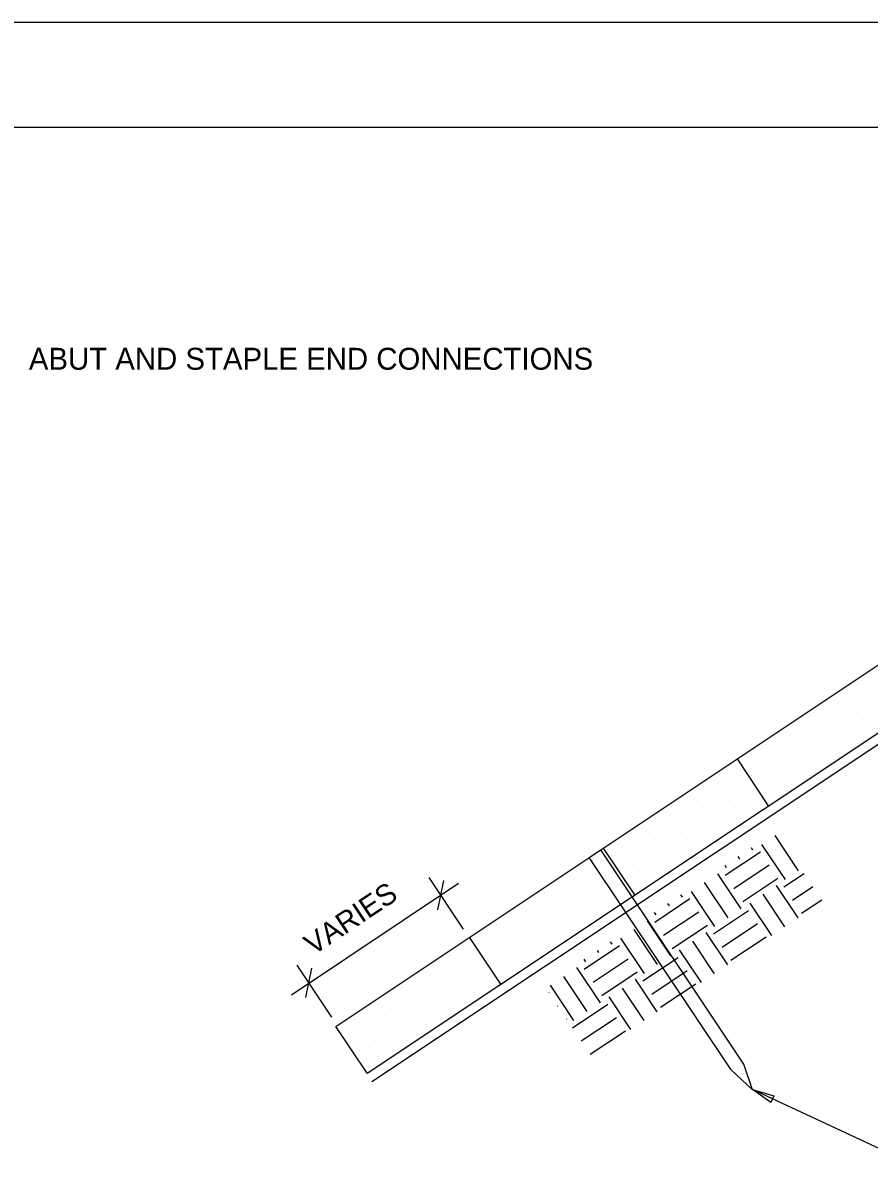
# Model space of a CAD drawing. Extents: x 638850 to 644908, y 297188 to 298900.
# Drawn here: x 641612.1 to 641721.5, y 297724.8 to 297871.3 of the extents above; entities that cross this region are included whole.
import ezdxf

# ---------------------------------------------------------------- set-up
doc = ezdxf.new("R2010")
doc.units = 0
for name, color, linetype in [('1', 7, 'Continuous'), ('11', 7, 'Continuous'), ('12', 7, 'Continuous'), ('3', 7, 'Continuous'), ('4', 7, 'Continuous'), ('5', 7, 'Continuous'), ('6', 7, 'Continuous'), ('7', 7, 'Continuous')]:
    doc.layers.add(name, color=color, linetype=linetype)

msp = doc.modelspace()

# ---------------------------------------------------------------- linework, layer by layer
at = {"layer": '1'}
for p, q in [((642242.46, 297871.34), (641270.46, 297871.34)), ((641310.96, 297857.84), (642228.96, 297857.84))]:
    msp.add_line(p, q, dxfattribs=at)
at = {"layer": '11'}
for p, q in [((641718.5, 297784.91), (641718.5, 297784.91)), ((641719.87, 297784.91), (641719.87, 297784.91)), ((641720.55, 297786.28), (641720.55, 297786.28)), ((641721.24, 297784.91), (641721.24, 297784.91)), ((641716.45, 297783.54), (641716.45, 297783.54)), ((641717.82, 297783.54), (641717.82, 297783.54)), ((641719.19, 297783.54), (641719.19, 297783.54)), ((641720.55, 297783.54), (641720.55, 297783.54)), ((641714.4, 297782.17), (641714.4, 297782.17)), ((641715.77, 297782.17), (641715.77, 297782.17)), ((641717.13, 297782.17), (641717.13, 297782.17)), ((641718.5, 297782.17), (641718.5, 297782.17)), ((641719.87, 297782.17), (641719.87, 297782.17)), ((641721.24, 297782.17), (641721.24, 297782.17)), ((641712.35, 297780.81), (641712.35, 297780.81)), ((641713.72, 297780.81), (641713.72, 297780.81)), ((641715.08, 297780.81), (641715.08, 297780.81)), ((641716.45, 297780.81), (641716.45, 297780.81)), ((641717.82, 297780.81), (641717.82, 297780.81)), ((641719.19, 297780.81), (641719.19, 297780.81)), ((641720.55, 297780.81), (641720.55, 297780.81)), ((641710.3, 297779.44), (641710.3, 297779.44)), ((641711.67, 297779.44), (641711.67, 297779.44)), ((641713.04, 297779.44), (641713.04, 297779.44)), ((641714.4, 297779.44), (641714.4, 297779.44)), ((641715.77, 297779.44), (641715.77, 297779.44)), ((641717.13, 297779.44), (641717.13, 297779.44)), ((641718.5, 297779.44), (641718.5, 297779.44)), ((641719.87, 297779.44), (641719.87, 297779.44)), ((641721.24, 297779.44), (641721.24, 297779.44)), ((641708.25, 297778.07), (641708.25, 297778.07)), ((641709.62, 297778.07), (641709.62, 297778.07)), ((641710.98, 297778.07), (641710.98, 297778.07)), ((641712.35, 297778.07), (641712.35, 297778.07)), ((641713.72, 297778.07), (641713.72, 297778.07)), ((641715.08, 297778.07), (641715.08, 297778.07)), ((641716.45, 297778.07), (641716.45, 297778.07)), ((641717.82, 297778.07), (641717.82, 297778.07)), ((641719.19, 297778.07), (641719.19, 297778.07)), ((641706.2, 297776.71), (641706.2, 297776.71)), ((641707.57, 297776.71), (641707.57, 297776.71)), ((641708.93, 297776.71), (641708.93, 297776.71)), ((641710.3, 297776.71), (641710.3, 297776.71)), ((641711.67, 297776.71), (641711.67, 297776.71)), ((641713.04, 297776.71), (641713.04, 297776.71)), ((641714.4, 297776.71), (641714.4, 297776.71)), ((641715.77, 297776.71), (641715.77, 297776.71)), ((641717.13, 297776.71), (641717.13, 297776.71)), ((641704.15, 297775.34), (641704.15, 297775.34)), ((641705.52, 297775.34), (641705.52, 297775.34)), ((641706.88, 297775.34), (641706.88, 297775.34)), ((641708.25, 297775.34), (641708.25, 297775.34)), ((641709.62, 297775.34), (641709.62, 297775.34)), ((641710.98, 297775.34), (641710.98, 297775.34)), ((641712.35, 297775.34), (641712.35, 297775.34)), ((641713.72, 297775.34), (641713.72, 297775.34)), ((641715.08, 297775.34), (641715.08, 297775.34)), ((641702.1, 297773.97), (641702.1, 297773.97)), ((641703.47, 297773.97), (641703.47, 297773.97)), ((641704.83, 297773.97), (641704.83, 297773.97)), ((641706.2, 297773.97), (641706.2, 297773.97)), ((641707.57, 297773.97), (641707.57, 297773.97)), ((641708.93, 297773.97), (641708.93, 297773.97)), ((641710.3, 297773.97), (641710.3, 297773.97)), ((641711.67, 297773.97), (641711.67, 297773.97)), ((641713.04, 297773.97), (641713.04, 297773.97)), ((641700.05, 297772.61), (641700.05, 297772.61)), ((641701.42, 297772.61), (641701.42, 297772.61)), ((641702.78, 297772.61), (641702.78, 297772.61)), ((641704.15, 297772.61), (641704.15, 297772.61)), ((641705.52, 297772.61), (641705.52, 297772.61)), ((641706.88, 297772.61), (641706.88, 297772.61)), ((641708.25, 297772.61), (641708.25, 297772.61)), ((641709.62, 297772.61), (641709.62, 297772.61)), ((641710.98, 297772.61), (641710.98, 297772.61)), ((641698, 297771.24), (641698, 297771.24)), ((641699.37, 297771.24), (641699.37, 297771.24)), ((641700.73, 297771.24), (641700.73, 297771.24)), ((641702.1, 297771.24), (641702.1, 297771.24)), ((641703.47, 297771.24), (641703.47, 297771.24)), ((641704.83, 297771.24), (641704.83, 297771.24)), ((641706.2, 297771.24), (641706.2, 297771.24)), ((641707.57, 297771.24), (641707.57, 297771.24)), ((641708.93, 297771.24), (641708.93, 297771.24)), ((641695.95, 297769.87), (641695.95, 297769.87)), ((641697.32, 297769.87), (641697.32, 297769.87)), ((641698.68, 297769.87), (641698.68, 297769.87)), ((641700.05, 297769.87), (641700.05, 297769.87)), ((641701.42, 297769.87), (641701.42, 297769.87)), ((641702.78, 297769.87), (641702.78, 297769.87)), ((641704.15, 297769.87), (641704.15, 297769.87)), ((641705.52, 297769.87), (641705.52, 297769.87)), ((641706.88, 297769.87), (641706.88, 297769.87)), ((641693.9, 297768.51), (641693.9, 297768.51)), ((641695.26, 297768.51), (641695.26, 297768.51)), ((641696.63, 297768.51), (641696.63, 297768.51)), ((641698, 297768.51), (641698, 297768.51)), ((641699.37, 297768.51), (641699.37, 297768.51)), ((641700.73, 297768.51), (641700.73, 297768.51)), ((641702.1, 297768.51), (641702.1, 297768.51)), ((641703.47, 297768.51), (641703.47, 297768.51)), ((641704.83, 297768.51), (641704.83, 297768.51)), ((641691.85, 297767.14), (641691.85, 297767.14)), ((641693.21, 297767.14), (641693.21, 297767.14)), ((641694.58, 297767.14), (641694.58, 297767.14)), ((641695.95, 297767.14), (641695.95, 297767.14)), ((641697.32, 297767.14), (641697.32, 297767.14)), ((641698.68, 297767.14), (641698.68, 297767.14)), ((641700.05, 297767.14), (641700.05, 297767.14)), ((641701.42, 297767.14), (641701.42, 297767.14)), ((641702.78, 297767.14), (641702.78, 297767.14)), ((641687.75, 297764.41), (641687.75, 297764.41)), ((641689.11, 297764.41), (641689.11, 297764.41)), ((641689.8, 297765.77), (641689.8, 297765.77)), ((641690.48, 297764.41), (641690.48, 297764.41)), ((641691.17, 297765.77), (641691.17, 297765.77)), ((641691.85, 297764.41), (641691.85, 297764.41)), ((641692.53, 297765.77), (641692.53, 297765.77)), ((641693.21, 297764.41), (641693.21, 297764.41)), ((641693.9, 297765.77), (641693.9, 297765.77)), ((641694.58, 297764.41), (641694.58, 297764.41)), ((641695.26, 297765.77), (641695.26, 297765.77)), ((641695.95, 297764.41), (641695.95, 297764.41)), ((641696.63, 297765.77), (641696.63, 297765.77)), ((641697.32, 297764.41), (641697.32, 297764.41)), ((641698, 297765.77), (641698, 297765.77)), ((641698.68, 297764.41), (641698.68, 297764.41)), ((641699.37, 297765.77), (641699.37, 297765.77)), ((641700.73, 297765.77), (641700.73, 297765.77)), ((641685.7, 297763.04), (641685.7, 297763.04)), ((641687.06, 297763.04), (641687.06, 297763.04)), ((641688.43, 297763.04), (641688.43, 297763.04)), ((641689.8, 297763.04), (641689.8, 297763.04)), ((641691.17, 297763.04), (641691.17, 297763.04)), ((641692.53, 297763.04), (641692.53, 297763.04)), ((641693.9, 297763.04), (641693.9, 297763.04)), ((641695.26, 297763.04), (641695.26, 297763.04)), ((641696.63, 297763.04), (641696.63, 297763.04)), ((641683.65, 297761.67), (641683.65, 297761.67)), ((641685.01, 297761.67), (641685.01, 297761.67)), ((641686.38, 297761.67), (641686.38, 297761.67)), ((641687.75, 297761.67), (641687.75, 297761.67)), ((641689.11, 297761.67), (641689.11, 297761.67)), ((641690.48, 297761.67), (641690.48, 297761.67)), ((641691.85, 297761.67), (641691.85, 297761.67)), ((641693.21, 297761.67), (641693.21, 297761.67)), ((641694.58, 297761.67), (641694.58, 297761.67)), ((641681.6, 297760.3), (641681.6, 297760.3)), ((641682.96, 297760.3), (641682.96, 297760.3)), ((641684.33, 297760.3), (641684.33, 297760.3)), ((641685.7, 297760.3), (641685.7, 297760.3)), ((641687.06, 297760.3), (641687.06, 297760.3)), ((641688.43, 297760.3), (641688.43, 297760.3)), ((641689.8, 297760.3), (641689.8, 297760.3)), ((641691.17, 297760.3), (641691.17, 297760.3)), ((641692.53, 297760.3), (641692.53, 297760.3)), ((641679.55, 297758.94), (641679.55, 297758.94)), ((641680.91, 297758.94), (641680.91, 297758.94)), ((641682.28, 297758.94), (641682.28, 297758.94)), ((641683.65, 297758.94), (641683.65, 297758.94)), ((641685.01, 297758.94), (641685.01, 297758.94)), ((641686.38, 297758.94), (641686.38, 297758.94)), ((641687.75, 297758.94), (641687.75, 297758.94)), ((641689.11, 297758.94), (641689.11, 297758.94)), ((641690.48, 297758.94), (641690.48, 297758.94)), ((641677.5, 297757.57), (641677.5, 297757.57)), ((641678.86, 297757.57), (641678.86, 297757.57)), ((641680.23, 297757.57), (641680.23, 297757.57)), ((641681.6, 297757.57), (641681.6, 297757.57)), ((641682.96, 297757.57), (641682.96, 297757.57)), ((641684.33, 297757.57), (641684.33, 297757.57)), ((641685.7, 297757.57), (641685.7, 297757.57)), ((641687.06, 297757.57), (641687.06, 297757.57)), ((641688.43, 297757.57), (641688.43, 297757.57)), ((641675.45, 297756.2), (641675.45, 297756.2)), ((641676.81, 297756.2), (641676.81, 297756.2)), ((641678.18, 297756.2), (641678.18, 297756.2)), ((641679.55, 297756.2), (641679.55, 297756.2)), ((641680.91, 297756.2), (641680.91, 297756.2)), ((641682.28, 297756.2), (641682.28, 297756.2)), ((641683.65, 297756.2), (641683.65, 297756.2)), ((641685.01, 297756.2), (641685.01, 297756.2)), ((641686.38, 297756.2), (641686.38, 297756.2)), ((641673.39, 297754.84), (641673.39, 297754.84)), ((641674.76, 297754.84), (641674.76, 297754.84)), ((641676.13, 297754.84), (641676.13, 297754.84)), ((641677.5, 297754.84), (641677.5, 297754.84)), ((641678.86, 297754.84), (641678.86, 297754.84)), ((641680.23, 297754.84), (641680.23, 297754.84)), ((641681.6, 297754.84), (641681.6, 297754.84)), ((641682.96, 297754.84), (641682.96, 297754.84)), ((641684.33, 297754.84), (641684.33, 297754.84)), ((641671.34, 297753.47), (641671.34, 297753.47)), ((641672.71, 297753.47), (641672.71, 297753.47)), ((641674.08, 297753.47), (641674.08, 297753.47)), ((641675.45, 297753.47), (641675.45, 297753.47)), ((641676.81, 297753.47), (641676.81, 297753.47)), ((641678.18, 297753.47), (641678.18, 297753.47)), ((641679.55, 297753.47), (641679.55, 297753.47)), ((641680.91, 297753.47), (641680.91, 297753.47)), ((641682.28, 297753.47), (641682.28, 297753.47)), ((641669.3, 297752.1), (641669.3, 297752.1)), ((641670.66, 297752.1), (641670.66, 297752.1)), ((641672.03, 297752.1), (641672.03, 297752.1)), ((641673.39, 297752.1), (641673.39, 297752.1)), ((641674.76, 297752.1), (641674.76, 297752.1)), ((641676.13, 297752.1), (641676.13, 297752.1)), ((641677.5, 297752.1), (641677.5, 297752.1)), ((641678.86, 297752.1), (641678.86, 297752.1)), ((641680.23, 297752.1), (641680.23, 297752.1)), ((641667.24, 297750.74), (641667.24, 297750.74)), ((641668.61, 297750.74), (641668.61, 297750.74)), ((641669.98, 297750.74), (641669.98, 297750.74)), ((641671.34, 297750.74), (641671.34, 297750.74)), ((641672.71, 297750.74), (641672.71, 297750.74)), ((641674.08, 297750.74), (641674.08, 297750.74)), ((641675.45, 297750.74), (641675.45, 297750.74)), ((641676.81, 297750.74), (641676.81, 297750.74)), ((641678.18, 297750.74), (641678.18, 297750.74)), ((641665.19, 297749.37), (641665.19, 297749.37)), ((641666.56, 297749.37), (641666.56, 297749.37)), ((641667.93, 297749.37), (641667.93, 297749.37)), ((641669.3, 297749.37), (641669.3, 297749.37)), ((641670.66, 297749.37), (641670.66, 297749.37)), ((641672.03, 297749.37), (641672.03, 297749.37)), ((641673.39, 297749.37), (641673.39, 297749.37)), ((641674.76, 297749.37), (641674.76, 297749.37)), ((641676.13, 297749.37), (641676.13, 297749.37)), ((641663.14, 297748), (641663.14, 297748)), ((641664.51, 297748), (641664.51, 297748)), ((641665.88, 297748), (641665.88, 297748)), ((641667.24, 297748), (641667.24, 297748)), ((641668.61, 297748), (641668.61, 297748)), ((641669.98, 297748), (641669.98, 297748)), ((641671.34, 297748), (641671.34, 297748)), ((641672.71, 297748), (641672.71, 297748)), ((641674.08, 297748), (641674.08, 297748)), ((641661.09, 297746.64), (641661.09, 297746.64)), ((641662.46, 297746.64), (641662.46, 297746.64)), ((641663.83, 297746.64), (641663.83, 297746.64)), ((641665.19, 297746.64), (641665.19, 297746.64)), ((641666.56, 297746.64), (641666.56, 297746.64)), ((641667.93, 297746.64), (641667.93, 297746.64)), ((641669.3, 297746.64), (641669.3, 297746.64)), ((641670.66, 297746.64), (641670.66, 297746.64)), ((641672.03, 297746.64), (641672.03, 297746.64)), ((641656.99, 297743.9), (641656.99, 297743.9)), ((641658.36, 297743.9), (641658.36, 297743.9)), ((641659.04, 297745.27), (641659.04, 297745.27)), ((641659.73, 297743.9), (641659.73, 297743.9)), ((641660.41, 297745.27), (641660.41, 297745.27)), ((641661.09, 297743.9), (641661.09, 297743.9)), ((641661.78, 297745.27), (641661.78, 297745.27)), ((641662.46, 297743.9), (641662.46, 297743.9)), ((641663.14, 297745.27), (641663.14, 297745.27)), ((641663.83, 297743.9), (641663.83, 297743.9)), ((641664.51, 297745.27), (641664.51, 297745.27)), ((641665.19, 297743.9), (641665.19, 297743.9)), ((641665.88, 297745.27), (641665.88, 297745.27)), ((641666.56, 297743.9), (641666.56, 297743.9)), ((641667.24, 297745.27), (641667.24, 297745.27)), ((641667.93, 297743.9), (641667.93, 297743.9)), ((641668.61, 297745.27), (641668.61, 297745.27)), ((641669.98, 297745.27), (641669.98, 297745.27)), ((641654.94, 297742.54), (641654.94, 297742.54)), ((641656.31, 297742.54), (641656.31, 297742.54)), ((641657.68, 297742.54), (641657.68, 297742.54)), ((641659.04, 297742.54), (641659.04, 297742.54)), ((641660.41, 297742.54), (641660.41, 297742.54)), ((641661.78, 297742.54), (641661.78, 297742.54)), ((641663.14, 297742.54), (641663.14, 297742.54)), ((641664.51, 297742.54), (641664.51, 297742.54)), ((641665.88, 297742.54), (641665.88, 297742.54)), ((641652.89, 297741.17), (641652.89, 297741.17)), ((641654.26, 297741.17), (641654.26, 297741.17)), ((641655.63, 297741.17), (641655.63, 297741.17)), ((641656.99, 297741.17), (641656.99, 297741.17)), ((641658.36, 297741.17), (641658.36, 297741.17)), ((641659.73, 297741.17), (641659.73, 297741.17)), ((641661.09, 297741.17), (641661.09, 297741.17)), ((641662.46, 297741.17), (641662.46, 297741.17)), ((641663.83, 297741.17), (641663.83, 297741.17)), ((641654.94, 297739.8), (641654.94, 297739.8)), ((641656.31, 297739.8), (641656.31, 297739.8)), ((641657.68, 297739.8), (641657.68, 297739.8)), ((641659.04, 297739.8), (641659.04, 297739.8)), ((641660.41, 297739.8), (641660.41, 297739.8)), ((641661.78, 297739.8), (641661.78, 297739.8)), ((641655.63, 297738.43), (641655.63, 297738.43)), ((641656.99, 297738.43), (641656.99, 297738.43)), ((641658.36, 297738.43), (641658.36, 297738.43)), ((641659.73, 297738.43), (641659.73, 297738.43)), ((641656.31, 297737.07), (641656.31, 297737.07)), ((641657.68, 297737.07), (641657.68, 297737.07))]:
    msp.add_line(p, q, dxfattribs=at)
at = {"layer": '12'}
for p, q in [((641712.33, 297761.72), (641709.3, 297766.27)), ((641706.45, 297764.37), (641706.25, 297764.69)), ((641710.63, 297760.58), (641707.59, 297765.13)), ((641702.85, 297761.15), (641707.4, 297764.18)), ((641704.75, 297763.24), (641704.54, 297763.55)), ((641703.04, 297762.1), (641702.84, 297762.41)), ((641703.99, 297759.44), (641708.54, 297762.48)), ((641703.24, 297755.65), (641700.2, 297760.2)), ((641704.94, 297756.79), (641701.91, 297761.34)), ((641705.13, 297757.74), (641709.68, 297760.77)), ((641710.44, 297759.64), (641713.06, 297761.38)), ((641697.36, 297758.31), (641697.15, 297758.62)), ((641701.53, 297754.52), (641698.49, 297759.06)), ((641710.58, 297754.49), (641707.78, 297758.69)), ((641712.29, 297755.62), (641709.49, 297759.82)), ((641711.57, 297757.93), (641714.19, 297759.68)), ((641693.76, 297755.08), (641698.31, 297758.12)), ((641695.65, 297757.17), (641695.44, 297757.48)), ((641708.88, 297753.35), (641706.08, 297757.55)), ((641712.71, 297756.22), (641715.33, 297757.97)), ((641693.95, 297756.03), (641693.74, 297756.34)), ((641694.89, 297753.38), (641699.44, 297756.41)), ((641701.34, 297753.57), (641705.89, 297756.6)), ((641694.14, 297749.59), (641691.1, 297754.14)), ((641695.84, 297750.72), (641692.81, 297755.27)), ((641696.03, 297751.67), (641700.58, 297754.7)), ((641702.48, 297751.86), (641707.03, 297754.89)), ((641692.43, 297748.45), (641689.4, 297753)), ((641701.49, 297748.42), (641698.69, 297752.62)), ((641703.19, 297749.56), (641700.39, 297753.76)), ((641703.61, 297750.15), (641708.16, 297753.19)), ((641684.66, 297749.02), (641689.21, 297752.05)), ((641686.56, 297751.1), (641686.35, 297751.41)), ((641688.26, 297752.24), (641688.05, 297752.55)), ((641699.78, 297747.28), (641696.98, 297751.48)), ((641684.85, 297749.96), (641684.64, 297750.28)), ((641685.8, 297747.31), (641690.35, 297750.34)), ((641692.24, 297747.5), (641696.79, 297750.53)), ((641686.75, 297744.66), (641683.71, 297749.2)), ((641686.94, 297745.6), (641691.48, 297748.64)), ((641693.38, 297745.79), (641697.93, 297748.83)), ((641683.33, 297742.38), (641680.3, 297746.93)), ((641685.04, 297743.52), (641682.01, 297748.07)), ((641694.09, 297743.49), (641691.29, 297747.69)), ((641694.52, 297744.09), (641699.06, 297747.12)), ((641680.07, 297745.96), (641680.11, 297745.98)), ((641690.68, 297741.21), (641687.88, 297745.41)), ((641692.39, 297742.35), (641689.59, 297746.55)), ((641681.21, 297744.25), (641681.25, 297744.28)), ((641683.14, 297741.43), (641687.69, 297744.47)), ((641682.35, 297742.54), (641682.39, 297742.57)), ((641684.28, 297739.73), (641688.83, 297742.76)), ((641685.42, 297738.02), (641689.97, 297741.05))]:
    msp.add_line(p, q, dxfattribs=at)
at = {"layer": '4'}
for p, q in [((641652.57, 297741.6), (641773.57, 297822.3)), ((641656.61, 297735.54), (641777.61, 297816.23)), ((641708.47, 297770.12), (641704.43, 297776.18)), ((641691.18, 297758.59), (641687.14, 297764.66)), ((641673.9, 297747.06), (641669.85, 297753.13)), ((641656.61, 297735.54), (641652.57, 297741.6))]:
    msp.add_line(p, q, dxfattribs=at)
at = {"layer": '5'}
for p, q in [((641646.83, 297745.7), (641668.42, 297760.1)), ((641669.08, 297754.19), (641664.63, 297760.86)), ((641665.77, 297756.69), (641666.52, 297760.48)), ((641666.14, 297758.59), (641666.14, 297758.59)), ((641652.04, 297742.82), (641647.59, 297749.5)), ((641648.72, 297745.33), (641649.48, 297749.12)), ((641724.93, 297724.81), (641706.37, 297733.43))]:
    msp.add_line(p, q, dxfattribs=at)
msp.add_lwpolyline([(641708.76, 297731.79), (641706.37, 297733.43), (641709.16, 297732.65)], close=True, dxfattribs=at)
at = {"layer": '6'}
for p, q in [((641685.31, 297763.42), (641686.8, 297764.42)), ((641705.28, 297736.71), (641686.8, 297764.42)), ((641703.62, 297735.98), (641685.31, 297763.42)), ((641706.37, 297733.42), (641705.28, 297736.71)), ((641703.62, 297735.98), (641706.37, 297733.42))]:
    msp.add_line(p, q, dxfattribs=at)
at = {"layer": '7'}
msp.add_line((641657.21, 297734.47), (641779.22, 297815.85), dxfattribs=at)

# ---------------------------------------------------------------- texts
at = {"layer": '3'}
msp.add_text('ABUT AND STAPLE END CONNECTIONS', height=2.835, dxfattribs=at).set_placement((641612.93, 297826.48))
msp.add_text('VARIES', height=2.723, rotation=33.7, dxfattribs=at).set_placement((641649.67, 297750.74))

doc.saveas('drawing.dxf')
